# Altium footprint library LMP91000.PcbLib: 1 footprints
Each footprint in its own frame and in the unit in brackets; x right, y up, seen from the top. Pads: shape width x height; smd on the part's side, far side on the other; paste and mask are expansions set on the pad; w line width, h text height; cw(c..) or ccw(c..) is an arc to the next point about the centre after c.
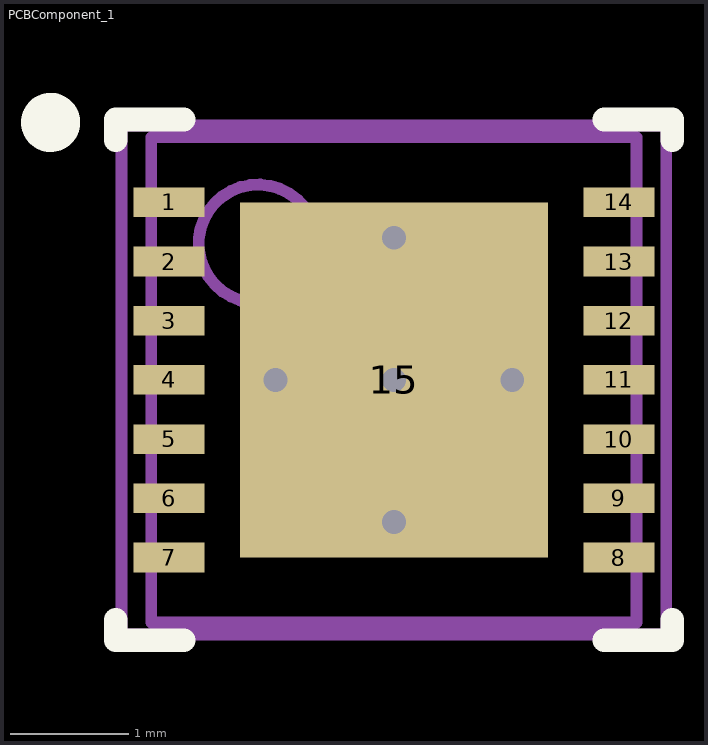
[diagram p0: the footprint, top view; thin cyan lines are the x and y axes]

## PCBComponent_1 [mm]
pads (15):
  rect 0.6x0.25 smd paste-0.125 mask+0.051: 1(-884.931,-816.888) 2(-884.931,-817.388) 3(-884.931,-817.888) 4(-884.931,-818.388) 5(-884.931,-818.888) 6(-884.931,-819.388) 7(-884.931,-819.888) 8(-881.131,-819.888) 9(-881.131,-819.388) 10(-881.131,-818.888) 11(-881.131,-818.388) 12(-881.131,-817.888) 13(-881.131,-817.388) 14(-881.131,-816.888)
  rect 2.6x3 smd paste-1.3 mask+0.051: 15(-883.031,-818.388)
via -883.031,-818.388 diameter 0.5 hole 0.2
via -882.031,-818.388 diameter 0.5 hole 0.2
via -884.031,-818.388 diameter 0.5 hole 0.2
via -883.031,-819.588 diameter 0.5 hole 0.2
via -883.031,-817.188 diameter 0.5 hole 0.2
Top Overlay:
  circle w0.25: c-885.931,-816.213 r0.125
  lines w0.2: -885.381,-820.413 -885.381,-820.588 -884.806,-820.588 ; -885.381,-816.363 -885.381,-816.188 -884.806,-816.188 ; -881.256,-820.588 -880.681,-820.588 -880.681,-820.413 ; -881.256,-816.188 -880.681,-816.188 -880.681,-816.363
Top Paste:
  region: -881.831,-816.988 -882.931,-816.988 -882.931,-818.288 -881.831,-818.288
  region: -881.831,-818.488 -882.931,-818.488 -882.931,-819.788 -881.831,-819.788
  rectangle: -884.231,-819.788 -883.131,-818.488
  rectangle: -884.231,-818.288 -883.131,-816.988
  region: -885.431,-819.763 -885.431,-820.013 -884.731,-820.013 -884.731,-819.763
  region: -885.431,-819.263 -885.431,-819.513 -884.731,-819.513 -884.731,-819.263
  region: -885.431,-818.763 -885.431,-819.013 -884.731,-819.013 -884.731,-818.763
  region: -885.431,-818.263 -885.431,-818.513 -884.731,-818.513 -884.731,-818.263
  region: -885.431,-817.263 -885.431,-817.513 -884.731,-817.513 -884.731,-817.263
  region: -885.431,-816.763 -885.431,-817.013 -884.731,-817.013 -884.731,-816.763
  region: -881.331,-816.763 -881.331,-817.013 -880.631,-817.013 -880.631,-816.763
  region: -881.331,-817.263 -881.331,-817.513 -880.631,-817.513 -880.631,-817.263
  region: -881.331,-817.763 -881.331,-818.013 -880.631,-818.013 -880.631,-817.763
  region: -881.331,-818.263 -881.331,-818.513 -880.631,-818.513 -880.631,-818.263
  region: -881.331,-818.763 -881.331,-819.013 -880.631,-819.013 -880.631,-818.763
  region: -881.331,-819.263 -881.331,-819.513 -880.631,-819.513 -880.631,-819.263
  region: -881.331,-819.763 -881.331,-820.013 -880.631,-820.013 -880.631,-819.763
  region: -885.431,-817.763 -885.431,-818.013 -884.731,-818.013 -884.731,-817.763
Mechanical 5:
  text ".Designator" at -884.555,-818.896 h1.02
Mechanical 13:
  circle w0.1: c-884.181,-817.238 r0.5
  lines w0.1: -885.081,-820.438 -885.081,-816.338 -880.981,-816.338 -880.981,-820.438 -885.081,-820.438
Mechanical 15:
  lines w0.1: -883.531,-818.388 -882.531,-818.388 ; -883.031,-818.888 -883.031,-817.888 ; -885.331,-820.538 -885.331,-816.238 -880.731,-816.238 -880.731,-820.538 -885.331,-820.538
3D body: height 0.8, standoff 0, extent -885.08,-820.437 -880.982,-816.339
